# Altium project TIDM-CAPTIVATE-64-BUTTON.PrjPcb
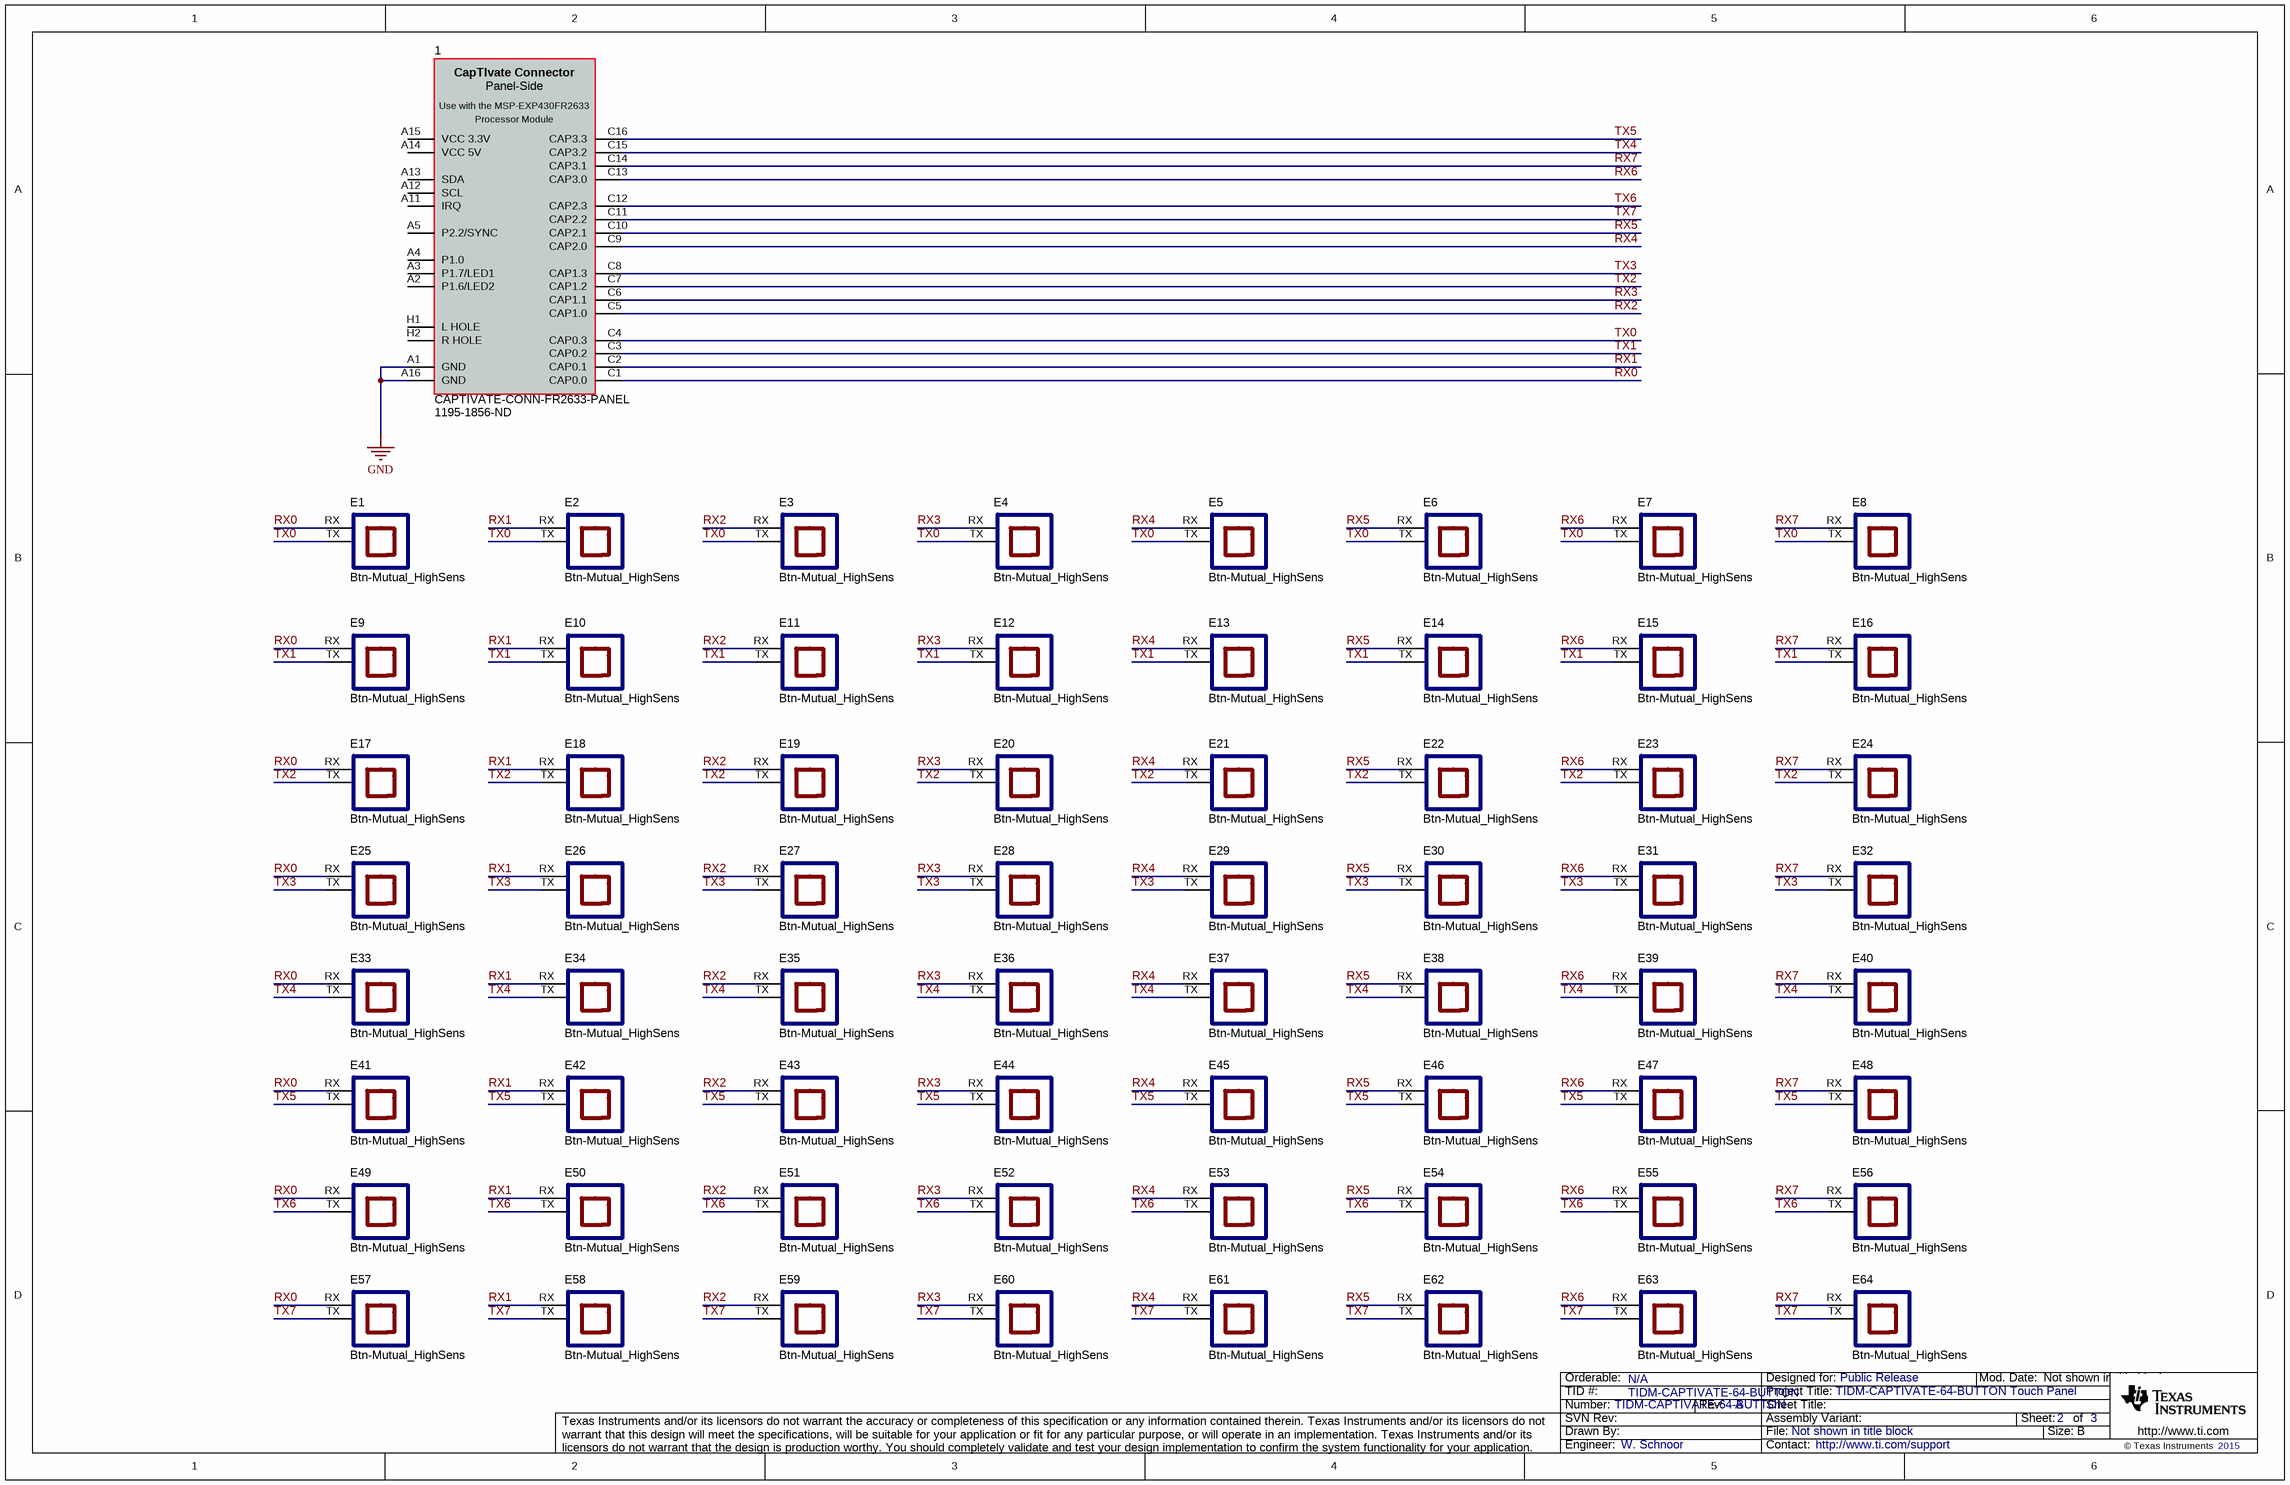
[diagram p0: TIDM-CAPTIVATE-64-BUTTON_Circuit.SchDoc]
CopyrightYear: 2015; EVM_orderable: N/A; PCB_Layout: W. Schnoor; PCB_Rev: 1.0; PRJ_Customer: Public Release; PRJ_Engineer: W. Schnoor; PRJ_Number: TIDM-CAPTIVATE-64-BUTTON; PRJ_Title: TIDM-CAPTIVATE-64-BUTTON Touch Panel; SCH_Rev: A; TechSupport: http://www.ti.com/support; TID: TIDM-CAPTIVATE-64-BUTTON
3 sheets, 75 parts. Net scope: global (net labels, ports and power ports of the same name join across sheets).
Board file: TIDM-CAPTIVATE-64-BUTTON_PCB.PcbDoc
Sheets:
  TIDM-CAPTIVATE-64-BUTTON_Circuit.SchDoc
  TIDM-CAPTIVATE-64-BUTTON_CoverSheet.SchDoc
  TIDM-CAPTIVATE-64-BUTTON_Hardware.SchDoc

## Sheet TIDM-CAPTIVATE-64-BUTTON_Circuit.SchDoc
size 431 x 279 mm; Date: Not shown in title block; ApprovedBy: Not shown in title block; CheckedBy: Not shown in title block; Author: Not shown in title block; CompanyName: Not shown in title block; Engineer: Not shown in title block; Organization: Not shown in title block; Address1: Not shown in title block; Address2: Not shown in title block; Address3: Not shown in title block; Address4: Not shown in title block; DocumentNumber: 1; Revision: Use project parameter SCH_Rev; SheetNumber: 2; SheetTotal: 3; PageSetup: Record=PageOptions¦CenterHorizontal=True¦CenterVertical=True¦PrintScale=0.62¦XCorrection=1.00¦YCorrection=1.00¦PrintKind=0¦BorderSize=5000000¦LeftOffset=0¦BottomOffset=0¦Orientation=2¦PaperLength=1000¦PaperWidth=1000¦Scale=100¦PaperSource=15¦PrintQuality=-3¦MediaType=1¦DitherType=10¦PrintScaleMode=1¦PaperKind=Letter¦PaperIndex=1

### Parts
1  CAPTIVATE-CONN-FR2633-PANEL  Supplier Part Number 1: 1195-1856-ND  [CAPTIVATE-CONN-48]
E1  Btn-Mutual_HighSens  [electrode-mutual-highsensitivity-cut-rotated]  (no BOM)
E2  Btn-Mutual_HighSens  [electrode-mutual-highsensitivity-cut-rotated]  (no BOM)
E3  Btn-Mutual_HighSens  [electrode-mutual-highsensitivity-cut-rotated]  (no BOM)
E4  Btn-Mutual_HighSens  [electrode-mutual-highsensitivity-cut-rotated]  (no BOM)
E5  Btn-Mutual_HighSens  [electrode-mutual-highsensitivity-cut-rotated]  (no BOM)
E6  Btn-Mutual_HighSens  [electrode-mutual-highsensitivity-cut-rotated]  (no BOM)
E7  Btn-Mutual_HighSens  [electrode-mutual-highsensitivity-cut-rotated]  (no BOM)
E8  Btn-Mutual_HighSens  [electrode-mutual-highsensitivity-cut-rotated]  (no BOM)
E9  Btn-Mutual_HighSens  [electrode-mutual-highsensitivity-cut-rotated]  (no BOM)
E10  Btn-Mutual_HighSens  [electrode-mutual-highsensitivity-cut-rotated]  (no BOM)
E11  Btn-Mutual_HighSens  [electrode-mutual-highsensitivity-cut-rotated]  (no BOM)
E12  Btn-Mutual_HighSens  [electrode-mutual-highsensitivity-cut-rotated]  (no BOM)
E13  Btn-Mutual_HighSens  [electrode-mutual-highsensitivity-cut-rotated]  (no BOM)
E14  Btn-Mutual_HighSens  [electrode-mutual-highsensitivity-cut-rotated]  (no BOM)
E15  Btn-Mutual_HighSens  [electrode-mutual-highsensitivity-cut-rotated]  (no BOM)
E16  Btn-Mutual_HighSens  [electrode-mutual-highsensitivity-cut-rotated]  (no BOM)
E17  Btn-Mutual_HighSens  [electrode-mutual-highsensitivity-cut-rotated]  (no BOM)
E18  Btn-Mutual_HighSens  [electrode-mutual-highsensitivity-cut-rotated]  (no BOM)
E19  Btn-Mutual_HighSens  [electrode-mutual-highsensitivity-cut-rotated]  (no BOM)
E20  Btn-Mutual_HighSens  [electrode-mutual-highsensitivity-cut-rotated]  (no BOM)
E21  Btn-Mutual_HighSens  [electrode-mutual-highsensitivity-cut-rotated]  (no BOM)
E22  Btn-Mutual_HighSens  [electrode-mutual-highsensitivity-cut-rotated]  (no BOM)
E23  Btn-Mutual_HighSens  [electrode-mutual-highsensitivity-cut-rotated]  (no BOM)
E24  Btn-Mutual_HighSens  [electrode-mutual-highsensitivity-cut-rotated]  (no BOM)
E25  Btn-Mutual_HighSens  [electrode-mutual-highsensitivity-cut-rotated]  (no BOM)
E26  Btn-Mutual_HighSens  [electrode-mutual-highsensitivity-cut-rotated]  (no BOM)
E27  Btn-Mutual_HighSens  [electrode-mutual-highsensitivity-cut-rotated]  (no BOM)
E28  Btn-Mutual_HighSens  [electrode-mutual-highsensitivity-cut-rotated]  (no BOM)
E29  Btn-Mutual_HighSens  [electrode-mutual-highsensitivity-cut-rotated]  (no BOM)
E30  Btn-Mutual_HighSens  [electrode-mutual-highsensitivity-cut-rotated]  (no BOM)
E31  Btn-Mutual_HighSens  [electrode-mutual-highsensitivity-cut-rotated]  (no BOM)
E32  Btn-Mutual_HighSens  [electrode-mutual-highsensitivity-cut-rotated]  (no BOM)
E33  Btn-Mutual_HighSens  [electrode-mutual-highsensitivity-cut-rotated]  (no BOM)
E34  Btn-Mutual_HighSens  [electrode-mutual-highsensitivity-cut-rotated]  (no BOM)
E35  Btn-Mutual_HighSens  [electrode-mutual-highsensitivity-cut-rotated]  (no BOM)
E36  Btn-Mutual_HighSens  [electrode-mutual-highsensitivity-cut-rotated]  (no BOM)
E37  Btn-Mutual_HighSens  [electrode-mutual-highsensitivity-cut-rotated]  (no BOM)
E38  Btn-Mutual_HighSens  [electrode-mutual-highsensitivity-cut-rotated]  (no BOM)
E39  Btn-Mutual_HighSens  [electrode-mutual-highsensitivity-cut-rotated]  (no BOM)
E40  Btn-Mutual_HighSens  [electrode-mutual-highsensitivity-cut-rotated]  (no BOM)
E41  Btn-Mutual_HighSens  [electrode-mutual-highsensitivity-cut-rotated]  (no BOM)
E42  Btn-Mutual_HighSens  [electrode-mutual-highsensitivity-cut-rotated]  (no BOM)
E43  Btn-Mutual_HighSens  [electrode-mutual-highsensitivity-cut-rotated]  (no BOM)
E44  Btn-Mutual_HighSens  [electrode-mutual-highsensitivity-cut-rotated]  (no BOM)
E45  Btn-Mutual_HighSens  [electrode-mutual-highsensitivity-cut-rotated]  (no BOM)
E46  Btn-Mutual_HighSens  [electrode-mutual-highsensitivity-cut-rotated]  (no BOM)
E47  Btn-Mutual_HighSens  [electrode-mutual-highsensitivity-cut-rotated]  (no BOM)
E48  Btn-Mutual_HighSens  [electrode-mutual-highsensitivity-cut-rotated]  (no BOM)
E49  Btn-Mutual_HighSens  [electrode-mutual-highsensitivity-cut-rotated]  (no BOM)
E50  Btn-Mutual_HighSens  [electrode-mutual-highsensitivity-cut-rotated]  (no BOM)
E51  Btn-Mutual_HighSens  [electrode-mutual-highsensitivity-cut-rotated]  (no BOM)
E52  Btn-Mutual_HighSens  [electrode-mutual-highsensitivity-cut-rotated]  (no BOM)
E53  Btn-Mutual_HighSens  [electrode-mutual-highsensitivity-cut-rotated]  (no BOM)
E54  Btn-Mutual_HighSens  [electrode-mutual-highsensitivity-cut-rotated]  (no BOM)
E55  Btn-Mutual_HighSens  [electrode-mutual-highsensitivity-cut-rotated]  (no BOM)
E56  Btn-Mutual_HighSens  [electrode-mutual-highsensitivity-cut-rotated]  (no BOM)
E57  Btn-Mutual_HighSens  [electrode-mutual-highsensitivity-cut-rotated]  (no BOM)
E58  Btn-Mutual_HighSens  [electrode-mutual-highsensitivity-cut-rotated]  (no BOM)
E59  Btn-Mutual_HighSens  [electrode-mutual-highsensitivity-cut-rotated]  (no BOM)
E60  Btn-Mutual_HighSens  [electrode-mutual-highsensitivity-cut-rotated]  (no BOM)
E61  Btn-Mutual_HighSens  [electrode-mutual-highsensitivity-cut-rotated]  (no BOM)
E62  Btn-Mutual_HighSens  [electrode-mutual-highsensitivity-cut-rotated]  (no BOM)
E63  Btn-Mutual_HighSens  [electrode-mutual-highsensitivity-cut-rotated]  (no BOM)
E64  Btn-Mutual_HighSens  [electrode-mutual-highsensitivity-cut-rotated]  (no BOM)

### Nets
GND: 1.A1(GND) 1.A16(GND)
RX0: 1.C1(CAP0.0) E1.RX E9.RX E17.RX E25.RX E33.RX E41.RX E49.RX E57.RX
RX1: 1.C2(CAP0.1) E2.RX E10.RX E18.RX E26.RX E34.RX E42.RX E50.RX E58.RX
RX2: 1.C5(CAP1.0) E3.RX E11.RX E19.RX E27.RX E35.RX E43.RX E51.RX E59.RX
RX3: 1.C6(CAP1.1) E4.RX E12.RX E20.RX E28.RX E36.RX E44.RX E52.RX E60.RX
RX4: 1.C9(CAP2.0) E5.RX E13.RX E21.RX E29.RX E37.RX E45.RX E53.RX E61.RX
RX5: 1.C10(CAP2.1) E6.RX E14.RX E22.RX E30.RX E38.RX E46.RX E54.RX E62.RX
RX6: 1.C13(CAP3.0) E7.RX E15.RX E23.RX E31.RX E39.RX E47.RX E55.RX E63.RX
RX7: 1.C14(CAP3.1) E8.RX E16.RX E24.RX E32.RX E40.RX E48.RX E56.RX E64.RX
TX0: 1.C4(CAP0.3) E1.TX E2.TX E3.TX E4.TX E5.TX E6.TX E7.TX E8.TX
TX1: 1.C3(CAP0.2) E9.TX E10.TX E11.TX E12.TX E13.TX E14.TX E15.TX E16.TX
TX2: 1.C7(CAP1.2) E17.TX E18.TX E19.TX E20.TX E21.TX E22.TX E23.TX E24.TX
TX3: 1.C8(CAP1.3) E25.TX E26.TX E27.TX E28.TX E29.TX E30.TX E31.TX E32.TX
TX4: 1.C15(CAP3.2) E33.TX E34.TX E35.TX E36.TX E37.TX E38.TX E39.TX E40.TX
TX5: 1.C16(CAP3.3) E41.TX E42.TX E43.TX E44.TX E45.TX E46.TX E47.TX E48.TX
TX6: 1.C12(CAP2.3) E49.TX E50.TX E51.TX E52.TX E53.TX E54.TX E55.TX E56.TX
TX7: 1.C11(CAP2.2) E57.TX E58.TX E59.TX E60.TX E61.TX E62.TX E63.TX E64.TX

Not connected (* = marked no-connect by the designer): 1 A2(P1.6/LED2) A3(P1.7/LED1) A4(P1.0) A5(P2.2/SYNC) A11(IRQ) A12(SCL) A13(SDA) A14(VCC_5V) A15(VCC_3.3V) H1(L_HOLE) H2(R_HOLE)

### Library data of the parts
1 = CAPTIVATE-CONN-MSP-EXP430FR2633-PANEL: CapTIvate Panel-Side Connector, 3x16, 100mil, TH, RA, M, MSP-EXP430FR2633; Manufacturer: Used in BOM report; SymbolCreator: a0273983; U/M: EA, IN, or GM
E1-E64 = btn-mutual-highsens: Capacitive Button, Mutual, 2-layer, 10mm, High Sensitivity; Manufacturer: None; SymbolCreator: a0273983; CompType: Electrode; U/M: EA, IN, or GM

## Sheet TIDM-CAPTIVATE-64-BUTTON_CoverSheet.SchDoc
size 431 x 279 mm; Date: Not shown in title block; ApprovedBy: Not shown in title block; CheckedBy: Not shown in title block; Author: Not shown in title block; CompanyName: Not shown in title block; Engineer: Not shown in title block; Organization: Not shown in title block; Address1: Not shown in title block; Address2: Not shown in title block; Address3: Not shown in title block; Address4: Not shown in title block; DocumentNumber: 1; Revision: Use project parameter SCH_Rev; SheetNumber: 1; SheetTotal: 3; PageSetup: Record=PageOptions¦CenterHorizontal=True¦CenterVertical=True¦PrintScale=1.00¦XCorrection=1.00¦YCorrection=1.00¦PrintKind=0¦BorderSize=5000000¦LeftOffset=0¦BottomOffset=0¦Orientation=2¦PaperLength=1000¦PaperWidth=1000¦Scale=100¦PaperSource=15¦PrintQuality=600¦MediaType=1¦DitherType=10¦PaperKind=Letter¦PrintScaleMode=1
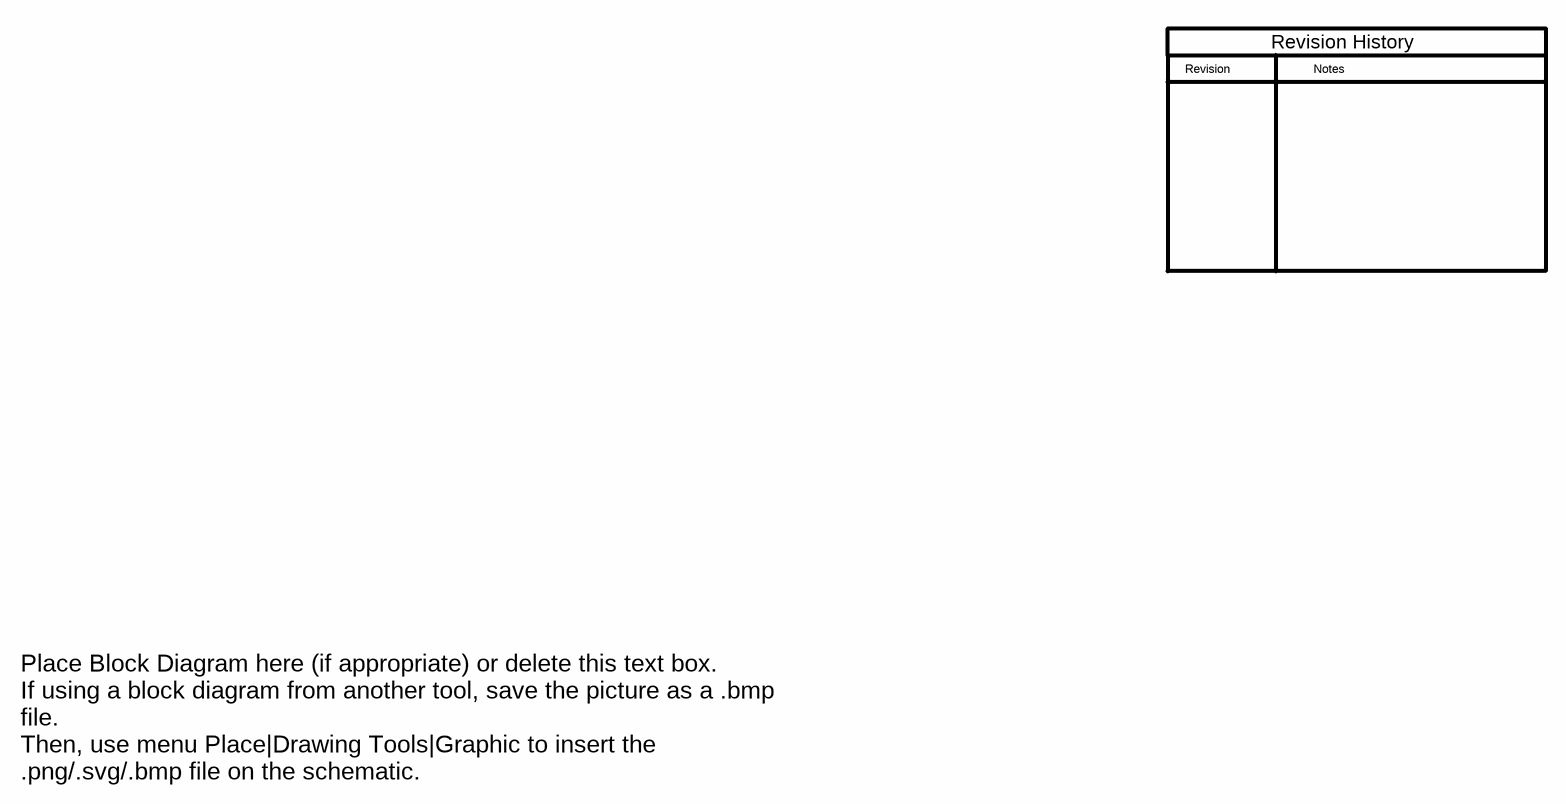
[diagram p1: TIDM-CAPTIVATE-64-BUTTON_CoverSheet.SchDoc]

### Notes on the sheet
- Revision
- Notes
- Revision History
- Place Block Diagram here (if appropriate) or delete this text box.
  If using a block diagram from another tool, save the picture as a .bmp file.
  Then, use menu Place|Drawing Tools|Graphic to insert the .png/.svg/.bmp file on the schematic.

## Sheet TIDM-CAPTIVATE-64-BUTTON_Hardware.SchDoc
size 431 x 279 mm; Date: Not shown in title block; ApprovedBy: Not shown in title block; CheckedBy: Not shown in title block; Author: Not shown in title block; CompanyName: Not shown in title block; Engineer: Not shown in title block; Organization: Not shown in title block; Address1: Not shown in title block; Address2: Not shown in title block; Address3: Not shown in title block; Address4: Not shown in title block; DocumentNumber: 1; Revision: Use project parameter SCH_Rev; SheetNumber: 3; SheetTotal: 3; PageSetup: Record=PageOptions¦CenterHorizontal=True¦CenterVertical=True¦PrintScale=1.00¦XCorrection=1.00¦YCorrection=1.00¦PrintKind=0¦BorderSize=5000000¦LeftOffset=0¦BottomOffset=0¦Orientation=2¦PaperLength=1000¦PaperWidth=1000¦Scale=100¦PaperSource=15¦PrintQuality=600¦MediaType=1¦DitherType=10¦PaperKind=Letter¦PrintScaleMode=1
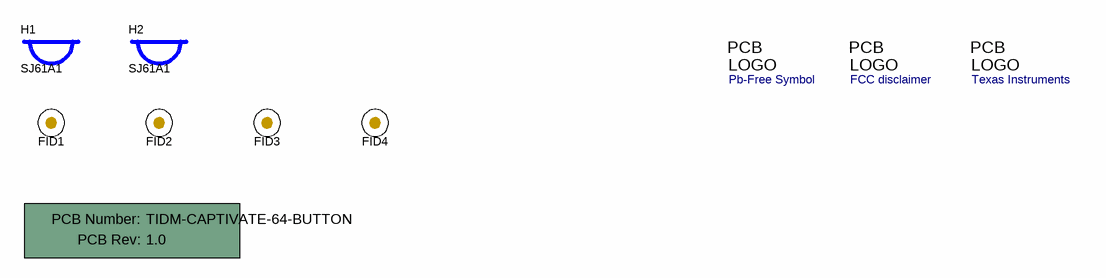
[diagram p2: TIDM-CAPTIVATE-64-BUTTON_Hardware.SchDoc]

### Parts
!PCB1  Printed Circuit Board  (value not drawn)  (mechanical)
FID1  Fiducial  [Fiducial10-20]  (value not drawn)
FID2  Fiducial  [Fiducial10-20]  (value not drawn)
FID3  Fiducial  [Fiducial10-20]  (value not drawn)
FID4  Fiducial  [Fiducial10-20]  (value not drawn)
H1  SJ61A1  [Bumpon_SJ61A1]
H2  SJ61A1  [Bumpon_SJ61A1]
Logo1  Pb-Free Symbol  [Pb-Free_Overlay_Small]  (no BOM)
Logo2  FCC disclaimer  [FCC_disclaimer]  (no BOM)
Logo3  Texas Instruments  [TI_Stacked_Overlay_Small]  (no BOM)

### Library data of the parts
!PCB1 = PCB: Manufacturer: Any; PartNumber: TIDM-CAPTIVATE-64-BUTTON; SymbolCreator: a0412235
FID1-FID4 = Fiducial: Fiducial mark.  There is nothing to buy or mount.; SymbolCreator: codlsc
H1 H2 = SJ61A1: Bumpon, Cylindrical, 0.312 X 0.200, Black; Manufacturer: 3M; SymbolCreator: a0412235
Logo1 = Pb-Free: SymbolCreator: a0412235
Logo2 = FCC_disclaimer: SymbolCreator: codlsc
Logo3 = TI_Logo: Texas Instrument Corporate Signature; SymbolCreator: a0412235

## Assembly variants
001: not fitted FID1 FID2 FID3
